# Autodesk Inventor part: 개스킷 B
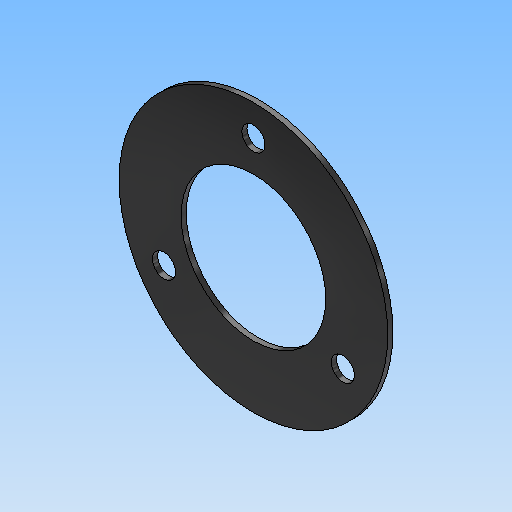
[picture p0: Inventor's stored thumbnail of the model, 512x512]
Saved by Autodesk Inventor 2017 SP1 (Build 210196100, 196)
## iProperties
Created: 2020-04
Part Number: 개스킷 B
Material: 고무
Document SubType Name: Modeling
Designer: mduedu
Density: 0.93 g/cm^3
Mass: 1.35803 g
Surface Area: 32.1424 cm^2
Volume: 1.46025 cm^3
Appearance: 고무 - 검은색 - 버전 1.1
Author: mduedu
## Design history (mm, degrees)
sketch "스케치1"
  geometry: C1 r 26 at (0, 0); 1 further point
  constraints: 1 centre point, 1 coincident
  dimensions: "d0" = 52 diameter of C1
extrude "돌출1" new body sketch "스케치1" distance "d1" = 1; taper "d2" = 0 deg
sketch "스케치3" dims "d6" = 40
  geometry: 3 further points
  constraints: 2 vertical alignment, 1 coincident, 2 other
hole "구멍1" sketch "스케치3" at (0, 20) diameter "d7" = 4.5; stored, may be unused: countersink angle "d11" = 90 deg, drill point angle "d13" = 118 deg; dims "d8" = 6, "d9" = 4, "d10" = 2, "d12" = 8
sketch "스케치4"
  geometry: C1 r 14 at (0, 0); 1 further point
  constraints: 1 centre point, 1 coincident
  dimensions: "d17" = 28 diameter of C1
extrude "돌출3" cut sketch "스케치4" stored distance "d18" = 1; taper "d19" = 0 deg
node "솔리드1"
pattern_circular "원형 패턴1" dims angle "d15" = 360 deg
